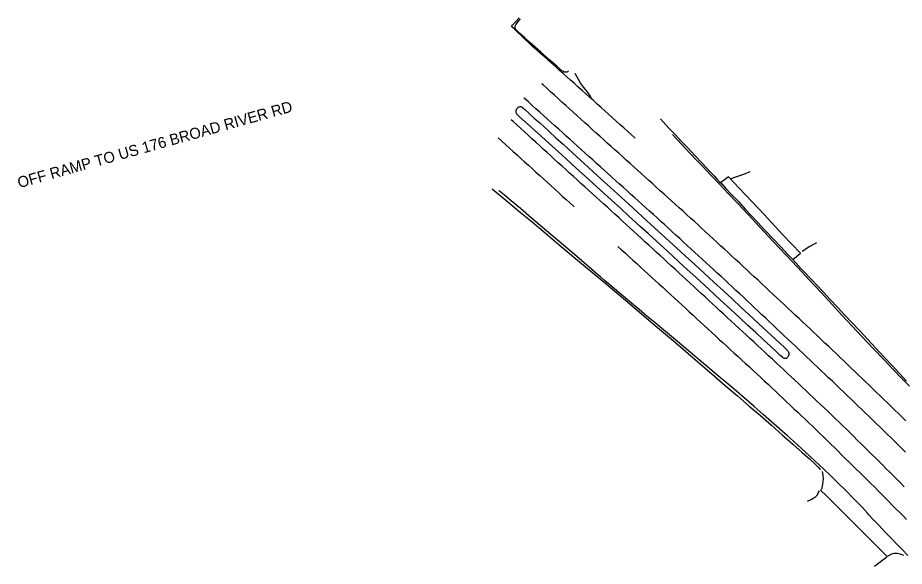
# Model space of a CAD drawing. Extents: x 1970211 to 1973046, y 801032 to 804001.
# Drawn here: x 1971645.8 to 1972080.5, y 802179.2 to 802448.3 of the extents above; entities that cross this region are included whole.
import ezdxf

# ---------------------------------------------------------------- set-up
doc = ezdxf.new("R2010")
doc.units = 0
for name, color, linetype in [('RD_EX_Conc', 7, 'Continuous'), ('RD_EX_Road', 7, 'Continuous'), ('RD_EX_Road_Paint', 7, 'Continuous'), ('RD_TX_RoadID', 7, 'Continuous')]:
    doc.layers.add(name, color=color, linetype=linetype)

msp = doc.modelspace()

# ---------------------------------------------------------------- linework, layer by layer
at = {"layer": 'RD_EX_Conc'}
for points in [[(1971915.93, 802422.26), (1971915.55, 802421.93), (1971915.32, 802421.78), (1971915.07, 802421.68), (1971914.81, 802421.62), (1971914.53, 802421.59), (1971914.24, 802421.61), (1971913.95, 802421.66), (1971913.65, 802421.75), (1971913.08, 802422.04), (1971912.62, 802422.33), (1971912.07, 802422.8), (1971910.09, 802424.55), (1971906.73, 802427.5), (1971905.13, 802428.92), (1971902.35, 802431.39), (1971896.92, 802436.25), (1971894.24, 802438.65), (1971892.06, 802440.57), (1971890.55, 802442), (1971890.1, 802442.52), (1971889.85, 802442.92), (1971889.74, 802443.25), (1971889.69, 802443.58), (1971889.7, 802443.9), (1971889.77, 802444.21), (1971890.02, 802444.82), (1971890.35, 802445.39), (1971891.18, 802446.47), (1971892.27, 802447.78)], [(1971960.92, 802398.71), (1971965.13, 802394.18), (1971968.32, 802390.82), (1971971.17, 802387.85), (1971974.37, 802384.49), (1971977.87, 802380.79), (1971981.61, 802376.78), (1971984.98, 802373.14), (1971987.4, 802370.55), (1971989, 802368.85), (1971989.92, 802367.88), (1971990.99, 802366.77), (1971993.02, 802364.62), (1971995.81, 802361.66), (1971999.15, 802358.1), (1972002.56, 802354.47), (1972005.51, 802351.32), (1972008.6, 802348.03), (1972012.36, 802344.01), (1972016.36, 802339.73), (1972020.14, 802335.7), (1972023.31, 802332.32), (1972025.5, 802329.99), (1972027.47, 802327.88), (1972030.02, 802325.18), (1972032.39, 802322.66), (1972033.84, 802321.11), (1972035.33, 802319.52), (1972037.8, 802316.9), (1972040.9, 802313.62), (1972044.24, 802310.06), (1972047.71, 802306.36), (1972051.19, 802302.64), (1972054.8, 802298.8), (1972058.66, 802294.7), (1972062.62, 802290.48), (1972066.56, 802286.27), (1972070.52, 802282.02), (1972074.56, 802277.66), (1972078.39, 802273.57), (1972081.68, 802270.1)], [(1972025.92, 802329.74), (1972027.73, 802331.25), (1972029.58, 802332.8), (1972020.88, 802342), (1972012.04, 802351.56), (1971999.77, 802364.55), (1971994.26, 802370.34), (1971992.3, 802368.77), (1971990.56, 802367.52)], [(1971878.36, 802364.39), (1971886.13, 802357.95), (1971892.39, 802352.76), (1971897.14, 802348.83), (1971904.37, 802342.83), (1971911.34, 802336.99), (1971921.31, 802328.61), (1971934.27, 802317.71), (1971947.04, 802306.96), (1971956.44, 802299.04), (1971962.47, 802293.94), (1971966.41, 802290.57), (1971970.75, 802286.82), (1971977.03, 802281.42), (1971982.65, 802276.6), (1971987.41, 802272.52), (1971992.74, 802267.94), (1971998.75, 802262.8), (1972004.51, 802257.84), (1972009.94, 802253.14), (1972015.37, 802248.39), (1972020.8, 802243.59), (1972025.91, 802239.09), (1972030.53, 802235.02), (1972034.02, 802231.91), (1972036.32, 802229.83), (1972037.71, 802228.53), (1972038.36, 802227.84), (1972039.08, 802226.92), (1972039.37, 802226.53)], [(1972080.36, 802184.49), (1972078.47, 802185.11), (1972076.96, 802185.45), (1972075.43, 802185.44), (1972074.18, 802185.16), (1972072.18, 802184), (1972064.28, 802191.91), (1972055.96, 802200.13), (1972048.28, 802207.85), (1972042.16, 802213.87), (1972039.67, 802216.43), (1972040.21, 802217.68), (1972040.52, 802219.51), (1972040.85, 802222.09), (1972040.79, 802223.79), (1972040.6, 802224.87), (1972040.35, 802225.78)]]:
    msp.add_lwpolyline(points, dxfattribs=at)
at = {"layer": 'RD_EX_Road'}
msp.add_lwpolyline([(1971899.42, 802398.81), (1971901.74, 802396.7), (1971906.04, 802392.78), (1971909.83, 802389.33), (1971913.19, 802386.28), (1971917.78, 802382.08), (1971923.72, 802376.65), (1971929.97, 802370.94), (1971936.45, 802365.04), (1971943.64, 802358.47), (1971947.53, 802354.9), (1971954.11, 802348.85), (1971957.87, 802345.4), (1971961.8, 802341.82), (1971968.89, 802335.37), (1971973.28, 802331.36), (1971977.79, 802327.24), (1971982.42, 802322.98), (1971987.17, 802318.6), (1971991.85, 802314.28), (1971996.26, 802310.2), (1972000.41, 802306.35), (1972004.29, 802302.75), (1972011.3, 802296.24), (1972017.35, 802290.64), (1972021.61, 802286.68), (1972023.27, 802285.06), (1972023.43, 802284.83), (1972023.58, 802284.59), (1972023.7, 802284.32), (1972023.87, 802283.76), (1972023.91, 802283.49), (1972023.92, 802283.24), (1972023.91, 802283.02), (1972023.87, 802282.81), (1972023.8, 802282.61), (1972023.72, 802282.44), (1972023.5, 802282.15), (1972023.3, 802281.83), (1972023.12, 802281.49), (1972023, 802281.36), (1972022.86, 802281.26), (1972022.69, 802281.19), (1972022.51, 802281.15), (1972022.31, 802281.14), (1972022.1, 802281.15), (1972021.87, 802281.19), (1972021.63, 802281.27), (1972021.37, 802281.39), (1972020.79, 802281.75), (1972019.69, 802282.68), (1972017.65, 802284.57), (1972014.84, 802287.21), (1972011.44, 802290.38), (1972007.7, 802293.86), (1972003.88, 802297.4), (1971999.84, 802301.13), (1971995.46, 802305.18), (1971990.47, 802309.78), (1971984.64, 802315.17), (1971978.46, 802320.87), (1971972.46, 802326.37), (1971967, 802331.37), (1971962.45, 802335.56), (1971959.04, 802338.7), (1971957.02, 802340.56), (1971954.87, 802342.52), (1971951.08, 802345.95), (1971945.2, 802351.3), (1971941.29, 802354.86), (1971936.73, 802359.02), (1971931.56, 802363.73), (1971925.8, 802368.97), (1971919.45, 802374.75), (1971912.51, 802381.05), (1971905.97, 802387), (1971900.8, 802391.69), (1971894.59, 802397.34), (1971891.9, 802399.79), (1971890.75, 802400.84), (1971890.57, 802401.03), (1971890.43, 802401.27), (1971890.31, 802401.55), (1971890.23, 802401.88), (1971890.18, 802402.22), (1971890.17, 802402.54), (1971890.21, 802402.86), (1971890.3, 802403.16), (1971890.42, 802403.45), (1971890.58, 802403.72), (1971890.77, 802403.97), (1971891, 802404.2), (1971891.25, 802404.4), (1971891.53, 802404.55), (1971891.82, 802404.66), (1971892.14, 802404.73), (1971892.46, 802404.74), (1971892.76, 802404.68), (1971893.05, 802404.54), (1971893.33, 802404.33), (1971894.43, 802403.33), (1971896.63, 802401.34)], close=True, dxfattribs=at)
for points in [[(1972083.01, 802267.54), (1972078.79, 802271.9), (1972075.1, 802275.72), (1972070.59, 802280.46), (1972065.18, 802286.16), (1972059.9, 802291.76), (1972054.88, 802297.12), (1972049.98, 802302.42), (1972045.07, 802307.74), (1972039.69, 802313.54), (1972033.85, 802319.79), (1972028.08, 802325.96), (1972022.39, 802332.05), (1972016.24, 802338.6), (1972009.74, 802345.52), (1972003.93, 802351.73), (1971998.91, 802357.13), (1971994.24, 802362.1), (1971989.9, 802366.66), (1971986.17, 802370.59), (1971983.2, 802373.73), (1971981.5, 802375.54), (1971980.78, 802376.31), (1971978.83, 802378.34), (1971975.43, 802381.9), (1971971.44, 802386.08), (1971966.82, 802391.06)], [(1972004.76, 802372.81), (1972001.67, 802371.36), (1971997.22, 802369.91), (1971995.49, 802369.38)], [(1972082.31, 802184.58), (1972079.52, 802187.42), (1972076.88, 802190.12), (1972074.07, 802193.04), (1972071.06, 802196.19), (1972067.97, 802199.38), (1972065.02, 802202.42), (1972063.3, 802204.32), (1972062.55, 802205.34), (1972060.08, 802208.01), (1972055.77, 802212.39), (1972051.62, 802216.54), (1972047.93, 802220.18), (1972044.5, 802223.55), (1972041.14, 802226.84), (1972036.87, 802230.85), (1972031.9, 802235.38), (1972028.33, 802238.63), (1972026.17, 802240.59), (1972023.26, 802243.19), (1972019.4, 802246.62), (1972015.39, 802250.15), (1972011.33, 802253.71), (1972006.88, 802257.63), (1972002.02, 802261.91), (1971997.07, 802266.17), (1971992.25, 802270.23), (1971988.66, 802273.22), (1971986.18, 802275.24), (1971982.99, 802277.92), (1971979.01, 802281.32), (1971975.54, 802284.26), (1971972.63, 802286.67), (1971969.27, 802289.47), (1971965.4, 802292.69), (1971961.68, 802295.8), (1971958.15, 802298.74), (1971954.47, 802301.83), (1971950.51, 802305.16), (1971945.81, 802309.11), (1971940.58, 802313.52), (1971936.37, 802317.08), (1971933.4, 802319.59), (1971931.53, 802321.2), (1971930.15, 802322.39), (1971925.92, 802326.03), (1971918.73, 802332.21), (1971911.3, 802338.57), (1971904.16, 802344.65), (1971897.77, 802350.07), (1971892.24, 802354.75), (1971887.8, 802358.47), (1971884.5, 802361.21), (1971882.05, 802363.24), (1971881.72, 802363.52)], [(1972037.46, 802337.89), (1972034.23, 802336.11), (1972030.52, 802333.65)], [(1972033.14, 802211.15), (1972034.81, 802212), (1972036.19, 802212.82), (1972037.09, 802213.49), (1972037.92, 802214.31), (1972038.36, 802215.18), (1972038.89, 802216.2)], [(1972065.97, 802179.23), (1972068.78, 802181.44), (1972071.89, 802183.8)]]:
    msp.add_lwpolyline(points, dxfattribs=at)
at = {"layer": 'RD_EX_Road_Paint'}
for points in [[(1971948.55, 802389.29), (1971946.69, 802390.96), (1971944.83, 802392.63), (1971942.97, 802394.3), (1971941.11, 802395.97), (1971939.24, 802397.64), (1971937.38, 802399.3), (1971935.52, 802400.97), (1971933.66, 802402.64), (1971931.8, 802404.31), (1971929.94, 802405.98), (1971928.07, 802407.65), (1971926.21, 802409.31), (1971924.35, 802410.98), (1971922.49, 802412.65), (1971920.63, 802414.32), (1971918.76, 802415.99), (1971916.9, 802417.66), (1971915.04, 802419.32), (1971913.18, 802420.99), (1971911.32, 802422.66), (1971909.45, 802424.33), (1971907.59, 802426), (1971905.73, 802427.67), (1971903.87, 802429.33), (1971902, 802430.99), (1971900.12, 802432.65), (1971898.25, 802434.3), (1971896.42, 802436), (1971894.6, 802437.72), (1971892.79, 802439.44), (1971890.97, 802441.16), (1971889.16, 802442.88), (1971887.89, 802444.07), (1971888.39, 802444.65), (1971890.03, 802446.53), (1971891.6, 802448.34)], [(1971918.98, 802421.11), (1971920.58, 802418.27), (1971921.81, 802416.1), (1971923.29, 802414.09), (1971924.77, 802412.07), (1971926.24, 802410.05), (1971926.81, 802409.28)], [(1972081.28, 802250.62), (1972079.49, 802252.36), (1972077.7, 802254.1), (1972075.9, 802255.84), (1972074.11, 802257.59), (1972072.32, 802259.33), (1972070.52, 802261.07), (1972068.73, 802262.81), (1972066.94, 802264.55), (1972065.14, 802266.29), (1972063.33, 802268.02), (1972061.52, 802269.74), (1972059.72, 802271.47), (1972057.91, 802273.2), (1972056.1, 802274.93), (1972054.29, 802276.65), (1972052.49, 802278.38), (1972050.68, 802280.11), (1972048.87, 802281.83), (1972047.06, 802283.56), (1972045.26, 802285.29), (1972043.45, 802287.02), (1972041.64, 802288.74), (1972039.83, 802290.47), (1972038.03, 802292.2), (1972036.22, 802293.92), (1972034.39, 802295.63), (1972032.57, 802297.34), (1972030.74, 802299.04), (1972028.91, 802300.75), (1972027.09, 802302.46), (1972025.26, 802304.16), (1972023.43, 802305.87), (1972021.6, 802307.58), (1972019.78, 802309.28), (1972017.95, 802310.99), (1972016.12, 802312.7), (1972014.3, 802314.4), (1972012.47, 802316.11), (1972010.64, 802317.82), (1972008.82, 802319.52), (1972006.99, 802321.23), (1972005.15, 802322.92), (1972003.31, 802324.62), (1972001.48, 802326.32), (1971999.64, 802328.01), (1971997.81, 802329.71), (1971995.97, 802331.4), (1971994.13, 802333.1), (1971992.3, 802334.8), (1971990.46, 802336.49), (1971988.62, 802338.19), (1971986.79, 802339.89), (1971984.95, 802341.58), (1971983.11, 802343.28), (1971981.28, 802344.98), (1971979.44, 802346.67), (1971977.6, 802348.36), (1971975.74, 802350.04), (1971973.89, 802351.71), (1971972.03, 802353.39), (1971970.17, 802355.06), (1971968.32, 802356.74), (1971966.46, 802358.41), (1971964.61, 802360.08), (1971962.75, 802361.76), (1971960.89, 802363.43), (1971959.04, 802365.11), (1971957.18, 802366.78), (1971955.32, 802368.46), (1971953.47, 802370.13), (1971951.61, 802371.81), (1971949.75, 802373.48), (1971947.9, 802375.16), (1971946.04, 802376.83), (1971944.18, 802378.5), (1971942.33, 802380.18), (1971940.47, 802381.85), (1971938.61, 802383.52), (1971936.75, 802385.19), (1971934.9, 802386.87), (1971933.04, 802388.54), (1971931.18, 802390.21), (1971929.32, 802391.89), (1971927.47, 802393.56), (1971925.61, 802395.24), (1971923.76, 802396.91), (1971921.9, 802398.59), (1971920.05, 802400.26), (1971918.19, 802401.94), (1971916.34, 802403.62), (1971914.49, 802405.3), (1971912.64, 802406.99), (1971910.79, 802408.67), (1971908.94, 802410.35), (1971907.09, 802412.03), (1971905.24, 802413.71), (1971903.39, 802415.39), (1971902.75, 802415.97)], [(1972081.18, 802235.2), (1972079.4, 802236.96), (1972077.62, 802238.71), (1972075.84, 802240.46), (1972074.04, 802242.2), (1972072.25, 802243.94), (1972070.45, 802245.68), (1972068.65, 802247.41), (1972066.86, 802249.15), (1972065.06, 802250.89), (1972063.26, 802252.63), (1972061.46, 802254.36), (1972059.67, 802256.1), (1972057.87, 802257.84), (1972056.07, 802259.58), (1972054.27, 802261.31), (1972052.48, 802263.05), (1972050.68, 802264.79), (1972048.88, 802266.52), (1972047.07, 802268.25), (1972045.25, 802269.97), (1972043.44, 802271.69), (1972041.63, 802273.41), (1972039.82, 802275.14), (1972038.01, 802276.86), (1972036.19, 802278.58), (1972034.38, 802280.3), (1972032.57, 802282.02), (1972030.76, 802283.75), (1972028.95, 802285.47), (1972027.13, 802287.19), (1972025.32, 802288.91), (1972023.5, 802290.62), (1972021.68, 802292.34), (1972019.85, 802294.05), (1972018.03, 802295.76), (1972016.21, 802297.47), (1972014.39, 802299.18), (1972012.57, 802300.9), (1972010.75, 802302.61), (1972008.92, 802304.32), (1972007.1, 802306.03), (1972005.28, 802307.74), (1972003.46, 802309.46), (1972001.64, 802311.17), (1971999.81, 802312.88), (1971997.99, 802314.59), (1971996.17, 802316.3), (1971994.34, 802318.01), (1971992.5, 802319.7), (1971990.66, 802321.39), (1971988.81, 802323.08), (1971986.97, 802324.77), (1971985.13, 802326.46), (1971983.29, 802328.15), (1971981.44, 802329.84), (1971979.6, 802331.53), (1971977.76, 802333.22), (1971975.92, 802334.91), (1971974.07, 802336.6), (1971972.23, 802338.29), (1971970.39, 802339.97), (1971968.55, 802341.66), (1971966.71, 802343.35), (1971964.86, 802345.04), (1971963.02, 802346.73), (1971961.18, 802348.42), (1971959.33, 802350.11), (1971957.47, 802351.78), (1971955.61, 802353.45), (1971953.76, 802355.13), (1971951.9, 802356.8), (1971950.04, 802358.48), (1971948.19, 802360.15), (1971946.33, 802361.82), (1971944.47, 802363.5), (1971942.62, 802365.17), (1971940.76, 802366.84), (1971938.9, 802368.52), (1971937.05, 802370.19), (1971935.19, 802371.87), (1971933.33, 802373.54), (1971931.47, 802375.21), (1971929.62, 802376.89), (1971927.76, 802378.56), (1971925.9, 802380.24), (1971924.05, 802381.91), (1971922.19, 802383.58), (1971920.33, 802385.26), (1971918.48, 802386.93), (1971916.62, 802388.61), (1971914.76, 802390.28), (1971912.91, 802391.95), (1971911.05, 802393.63), (1971909.19, 802395.3), (1971907.34, 802396.97), (1971905.48, 802398.65), (1971903.62, 802400.32), (1971901.76, 802402), (1971899.91, 802403.67), (1971898.05, 802405.34), (1971896.19, 802407.02), (1971894.34, 802408.69), (1971893.94, 802409.05)], [(1972080.55, 802218.27), (1972078.78, 802220.03), (1972077.01, 802221.8), (1972075.24, 802223.56), (1972073.47, 802225.33), (1972071.7, 802227.1), (1972069.93, 802228.86), (1972068.15, 802230.62), (1972066.38, 802232.38), (1972064.6, 802234.13), (1972062.82, 802235.89), (1972061.05, 802237.65), (1972059.27, 802239.41), (1972057.49, 802241.17), (1972055.72, 802242.93), (1972053.94, 802244.69), (1972052.17, 802246.45), (1972050.37, 802248.18), (1972048.56, 802249.91), (1972046.75, 802251.64), (1972044.94, 802253.36), (1972043.13, 802255.09), (1972041.33, 802256.82), (1972039.52, 802258.54), (1972037.71, 802260.27), (1972035.89, 802261.99), (1972034.07, 802263.7), (1972032.25, 802265.42), (1972030.43, 802267.13), (1972028.61, 802268.84), (1972026.79, 802270.56), (1972024.97, 802272.27), (1972023.15, 802273.98), (1972021.32, 802275.69), (1972019.49, 802277.39), (1972017.66, 802279.09), (1972015.83, 802280.79), (1972014, 802282.5), (1972012.17, 802284.2), (1972010.34, 802285.9), (1972008.5, 802287.6), (1972006.67, 802289.3), (1972004.83, 802291), (1972003, 802292.69), (1972001.16, 802294.39), (1971999.32, 802296.09), (1971997.49, 802297.78), (1971995.65, 802299.48), (1971993.82, 802301.17), (1971991.98, 802302.87), (1971990.14, 802304.57), (1971988.31, 802306.26), (1971986.47, 802307.96), (1971984.64, 802309.66), (1971982.8, 802311.36), (1971980.96, 802313.05), (1971979.13, 802314.75), (1971977.29, 802316.45), (1971975.46, 802318.14), (1971973.62, 802319.84), (1971971.78, 802321.53), (1971969.93, 802323.22), (1971968.09, 802324.91), (1971966.25, 802326.6), (1971964.41, 802328.29), (1971962.57, 802329.98), (1971960.73, 802331.68), (1971958.89, 802333.37), (1971957.05, 802335.06), (1971955.21, 802336.75), (1971953.36, 802338.44), (1971951.52, 802340.13), (1971949.68, 802341.82), (1971947.84, 802343.51), (1971946, 802345.2), (1971944.16, 802346.9), (1971942.32, 802348.59), (1971940.47, 802350.28), (1971938.62, 802351.96), (1971936.77, 802353.64), (1971934.92, 802355.32), (1971933.07, 802357), (1971931.22, 802358.68), (1971929.37, 802360.36), (1971927.52, 802362.04), (1971925.67, 802363.72), (1971923.82, 802365.41), (1971921.97, 802367.09), (1971920.12, 802368.77), (1971918.27, 802370.45), (1971916.42, 802372.13), (1971914.57, 802373.81), (1971912.72, 802375.49), (1971910.87, 802377.17), (1971909.02, 802378.85), (1971907.17, 802380.54), (1971905.32, 802382.22), (1971903.47, 802383.9), (1971901.63, 802385.59), (1971899.79, 802387.28), (1971897.95, 802388.97), (1971896.11, 802390.67), (1971894.26, 802392.36), (1971892.42, 802394.05), (1971890.58, 802395.74), (1971888.74, 802397.43), (1971887.8, 802398.3)], [(1971881.35, 802389.42), (1971883.2, 802387.74), (1971885.06, 802386.06), (1971886.91, 802384.38), (1971888.76, 802382.7), (1971890.61, 802381.02), (1971892.46, 802379.34), (1971894.31, 802377.67), (1971896.17, 802375.99), (1971898.02, 802374.31), (1971899.87, 802372.63), (1971901.72, 802370.95), (1971903.57, 802369.27), (1971905.43, 802367.59), (1971907.28, 802365.91), (1971909.13, 802364.23), (1971910.98, 802362.55), (1971912.83, 802360.87), (1971914.68, 802359.19), (1971916.54, 802357.51), (1971918.39, 802355.83), (1971918.65, 802355.59)], [(1971940.05, 802336.13), (1971941.9, 802334.45), (1971943.75, 802332.76), (1971945.59, 802331.08), (1971947.44, 802329.4), (1971949.29, 802327.71), (1971951.14, 802326.03), (1971952.98, 802324.34), (1971954.83, 802322.65), (1971956.67, 802320.97), (1971958.52, 802319.28), (1971960.36, 802317.59), (1971962.21, 802315.91), (1971964.06, 802314.22), (1971965.9, 802312.54), (1971967.75, 802310.85), (1971969.59, 802309.16), (1971971.43, 802307.47), (1971973.26, 802305.77), (1971975.1, 802304.07), (1971976.93, 802302.37), (1971978.77, 802300.68), (1971980.61, 802298.99), (1971982.45, 802297.3), (1971984.29, 802295.6), (1971986.14, 802293.91), (1971987.98, 802292.22), (1971989.82, 802290.53), (1971991.66, 802288.84), (1971993.5, 802287.15), (1971995.34, 802285.45), (1971997.18, 802283.76), (1971999.02, 802282.07), (1972000.86, 802280.38), (1972002.7, 802278.69), (1972004.54, 802277), (1972006.38, 802275.3), (1972008.22, 802273.61), (1972010.07, 802271.92), (1972011.89, 802270.21), (1972013.71, 802268.5), (1972015.53, 802266.78), (1972017.34, 802265.06), (1972019.16, 802263.35), (1972020.98, 802261.63), (1972022.79, 802259.91), (1972024.61, 802258.2), (1972026.43, 802256.48), (1972028.25, 802254.76), (1972030.06, 802253.05), (1972031.88, 802251.33), (1972033.7, 802249.61), (1972035.51, 802247.89), (1972037.33, 802246.18), (1972039.12, 802244.43), (1972040.91, 802242.68), (1972042.69, 802240.93), (1972044.47, 802239.17), (1972046.25, 802237.42), (1972048.03, 802235.67), (1972049.82, 802233.92), (1972051.6, 802232.16), (1972053.38, 802230.41), (1972055.16, 802228.66), (1972056.95, 802226.9), (1972058.73, 802225.15), (1972060.51, 802223.4), (1972062.29, 802221.64), (1972064.07, 802219.89), (1972065.86, 802218.14), (1972067.62, 802216.36), (1972069.38, 802214.58), (1972071.13, 802212.81), (1972072.89, 802211.03), (1972074.64, 802209.25), (1972076.4, 802207.47), (1972078.16, 802205.69), (1972079.91, 802203.91), (1972081.67, 802202.13)]]:
    msp.add_lwpolyline(points, dxfattribs=at)

# ---------------------------------------------------------------- texts
at = {"layer": 'RD_TX_RoadID'}
msp.add_text('OFF RAMP TO US 176 BROAD RIVER RD', height=5.4, rotation=15.6741, dxfattribs=at).set_placement((1971646.51, 802364.68))

doc.saveas('drawing.dxf')
